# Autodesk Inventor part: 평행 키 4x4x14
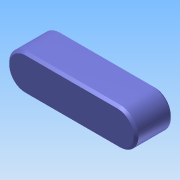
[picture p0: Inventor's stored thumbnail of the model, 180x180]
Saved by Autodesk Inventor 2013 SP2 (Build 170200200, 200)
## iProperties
Created: 2026-07
Part Number: 평행 키 4x4x14
Material: Generic
Document SubType Name: Modeling
Designer: 601
Density: 1 g/cm^3
Author: 601
변환 표준: STEP AP214IS
전처리기: Build: 200, Release: 2013 SP2 Update 6 - Date: Thu 07/17/2014
전송 단위: 밀리미터
불확실성: 0.01
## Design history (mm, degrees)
node "평행 키 4x4x141"
node "솔리드1"
node "기준1"
